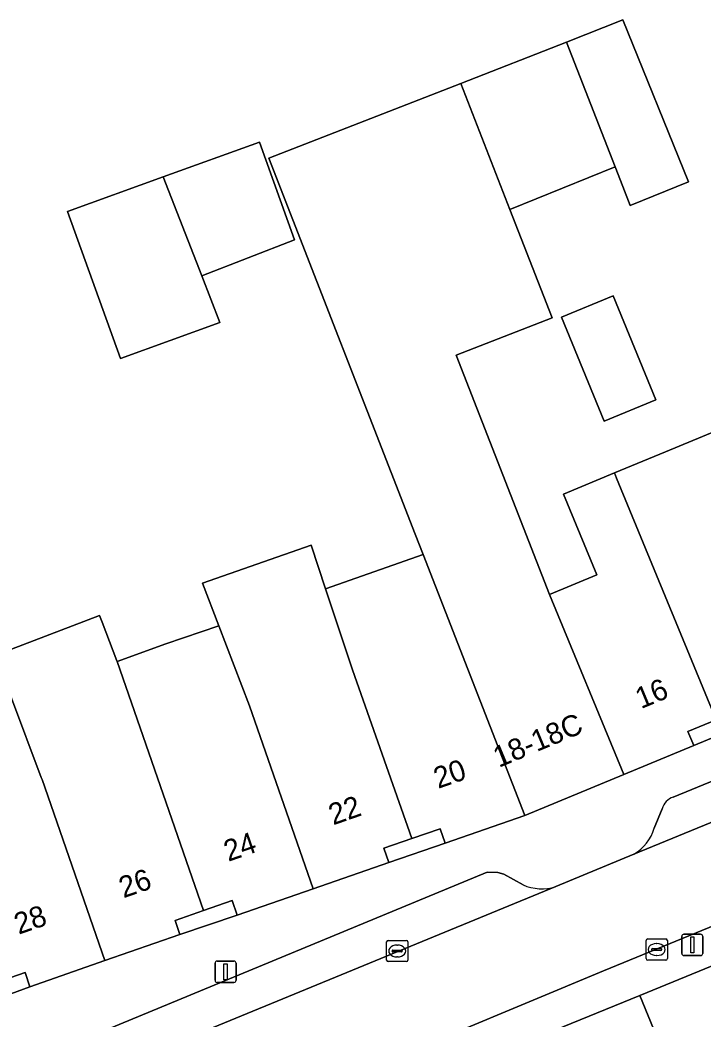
# Model space of a CAD drawing. Extents: x 159371 to 159986, y 382987 to 383597.
# Drawn here: x 159845.76 to 159877.92, y 383356.32 to 383403.35 of the extents above; entities that cross this region are included whole.
import ezdxf

# ---------------------------------------------------------------- set-up
doc = ezdxf.new("R2010")
doc.units = 0
for name, color, linetype in [('IMGEO_Erf', 7, 'Continuous'), ('IMGEO_Kolk', 7, 'Continuous'), ('IMGEO_Lichtmast', 7, 'Continuous'), ('IMGEO_Pand', 7, 'Continuous'), ('IMGEO_Pand_nummerreeks', 7, 'Continuous'), ('IMGEO_Parkeervlak_open', 7, 'Continuous'), ('IMGEO_Rijbaan_lokaal_open', 7, 'Continuous'), ('IMGEO_Voetpad_open', 7, 'Continuous')]:
    doc.layers.add(name, color=color, linetype=linetype)

msp = doc.modelspace()

# ---------------------------------------------------------------- linework, layer by layer
at = {"layer": 'IMGEO_Erf'}
msp.add_lwpolyline([(159844.604, 383373.459), (159849.507, 383375.324), (159849.63, 383375), (159850.322, 383373.18), (159850.332, 383373.15), (159852.636, 383373.984), (159855.129, 383374.826), (159854.362, 383376.837), (159859.474, 383378.624), (159860.151, 383376.581), (159864.746, 383378.187), (159864.374, 383379.142), (159857.484, 383396.843), (159866.523, 383400.361), (159871.498, 383402.313), (159874.144, 383403.352), (159877.244, 383395.735), (159874.499, 383394.618), (159874.152, 383395.509), (159873.786, 383396.446), (159868.832, 383394.43), (159870.814, 383389.337), (159866.298, 383387.579), (159870.687, 383376.303), (159872.924, 383377.231), (159871.349, 383381.03), (159873.758, 383382.028), (159876.16, 383383.024), (159878.542, 383384.012)], dxfattribs=at)
for points in [[(159852.508, 383395.963), (159857.034, 383397.596), (159858.688, 383393.009), (159854.324, 383391.307), (159855.181, 383389.109), (159850.492, 383387.418), (159847.997, 383394.337)], [(159871.261, 383389.365), (159873.687, 383390.362), (159875.7, 383385.467), (159873.274, 383384.47)]]:
    msp.add_lwpolyline(points, close=True, dxfattribs=at)
at = {"layer": 'IMGEO_Kolk'}
for p, q in [((159863.022, 383359.098), (159863.022, 383359.95)), ((159863.097, 383360.024), (159863.949, 383360.024)), ((159863.51, 383359.804), (159863.535, 383359.804)), ((159864.023, 383359.95), (159864.023, 383359.098)), ((159875.241, 383359.169), (159875.241, 383360.021)), ((159875.316, 383360.095), (159876.168, 383360.095)), ((159875.729, 383359.875), (159875.754, 383359.875)), ((159876.242, 383360.021), (159876.242, 383359.169)), ((159863.281, 383359.518), (159863.281, 383359.53)), ((159863.719, 383359.481), (159863.321, 383359.481)), ((159863.324, 383359.567), (159863.722, 383359.567)), ((159863.533, 383359.244), (159863.508, 383359.244)), ((159863.765, 383359.53), (159863.765, 383359.518)), ((159875.5, 383359.589), (159875.5, 383359.601)), ((159875.938, 383359.552), (159875.54, 383359.552)), ((159875.543, 383359.638), (159875.941, 383359.638)), ((159875.752, 383359.315), (159875.727, 383359.315)), ((159875.984, 383359.601), (159875.984, 383359.589)), ((159863.949, 383359.024), (159863.097, 383359.024)), ((159876.168, 383359.095), (159875.316, 383359.095))]:
    msp.add_line(p, q, dxfattribs=at)
for points in [[(159863.022, 383359.098), (159863.022, 383359.95)], [(159863.097, 383360.024), (159863.949, 383360.024)], [(159864.023, 383359.95), (159864.023, 383359.098)], [(159875.241, 383359.169), (159875.241, 383360.021)], [(159875.316, 383360.095), (159876.168, 383360.095)], [(159876.242, 383360.021), (159876.242, 383359.169)], [(159863.949, 383359.024), (159863.097, 383359.024)], [(159876.168, 383359.095), (159875.316, 383359.095)]]:
    msp.add_lwpolyline(points, dxfattribs=at)
for centre, radius, start, end in [((159863.099, 383359.948), 0.0765, 91.552, 178.448), ((159863.099, 383359.948), 0.0765, 91.552, 178.448), ((159863.947, 383359.948), 0.0765, 1.552, 88.448), ((159863.947, 383359.948), 0.0765, 1.552, 88.448), ((159875.318, 383360.019), 0.0765, 91.552, 178.448), ((159875.318, 383360.019), 0.0765, 91.552, 178.448), ((159876.166, 383360.019), 0.0765, 1.552, 88.448), ((159876.166, 383360.019), 0.0765, 1.552, 88.448), ((159863.321, 383359.527), 0.0403, 85.8775, 175.7526), ((159863.318, 383359.517), 0.0366, 178.938, 274.7102), ((159863.722, 383359.524), 0.043, 264.8664, 352.4533), ((159863.726, 383359.529), 0.0386, 1.7309, 96.639), ((159875.54, 383359.598), 0.0403, 85.8775, 175.7526), ((159875.537, 383359.588), 0.0366, 178.938, 274.7102), ((159875.941, 383359.595), 0.043, 264.8664, 352.4533), ((159875.945, 383359.6), 0.0386, 1.7309, 96.639), ((159863.099, 383359.1), 0.0765, 181.552, 268.448), ((159863.099, 383359.1), 0.0765, 181.552, 268.448), ((159863.947, 383359.1), 0.0765, 271.552, 358.448), ((159863.947, 383359.1), 0.0765, 271.552, 358.448), ((159875.318, 383359.171), 0.0765, 181.552, 268.448), ((159875.318, 383359.171), 0.0765, 181.552, 268.448), ((159876.166, 383359.171), 0.0765, 271.552, 358.448), ((159876.166, 383359.171), 0.0765, 271.552, 358.448)]:
    msp.add_arc(centre, radius, start, end, dxfattribs=at)
for centre, major_axis, ratio, start_param, end_param in [((159863.509, 383359.524), (-0.387, 0.002), 0.722429, 4.712389, 7.853982), ((159863.534, 383359.524), (-0.39, 0.002), 0.717154, 1.570796, 4.712389), ((159875.728, 383359.595), (-0.387, 0.002), 0.722429, 4.712389, 7.853982), ((159875.753, 383359.595), (-0.39, 0.002), 0.717154, 1.570796, 4.712389)]:
    msp.add_ellipse(centre, major_axis=major_axis, ratio=ratio, start_param=start_param, end_param=end_param, dxfattribs=at)
at = {"layer": 'IMGEO_Lichtmast'}
for p, q in [((159876.92, 383359.411), (159876.92, 383360.211)), ((159876.92, 383360.211), (159876.92, 383359.411)), ((159877.02, 383360.311), (159877.81, 383360.311)), ((159877.81, 383360.311), (159877.02, 383360.311)), ((159877.91, 383360.211), (159877.91, 383359.411)), ((159877.91, 383359.411), (159877.91, 383360.211)), ((159877.81, 383359.311), (159877.02, 383359.311)), ((159877.02, 383359.311), (159877.81, 383359.311)), ((159854.947, 383358.15), (159854.947, 383358.95)), ((159854.947, 383358.95), (159854.947, 383358.15)), ((159855.047, 383359.05), (159855.837, 383359.05)), ((159855.837, 383359.05), (159855.047, 383359.05)), ((159855.937, 383358.95), (159855.937, 383358.15)), ((159855.937, 383358.15), (159855.937, 383358.95)), ((159855.837, 383358.05), (159855.047, 383358.05)), ((159855.047, 383358.05), (159855.837, 383358.05))]:
    msp.add_line(p, q, dxfattribs=at)
for points in [[(159877.34, 383360.186), (159877.49, 383360.186), (159877.49, 383359.436), (159877.34, 383359.436), (159877.34, 383360.186)], [(159855.367, 383358.925), (159855.517, 383358.925), (159855.517, 383358.175), (159855.367, 383358.175), (159855.367, 383358.925)]]:
    msp.add_lwpolyline(points, dxfattribs=at)
for centre, start, end in [((159877.02, 383360.211), 90, 180), ((159877.02, 383360.211), 90, 180), ((159877.81, 383360.211), 0, 90), ((159877.81, 383360.211), 360, 90), ((159877.02, 383359.411), 180, 270), ((159877.02, 383359.411), 180, 270), ((159877.81, 383359.411), 270, 0), ((159877.81, 383359.411), 270, 0), ((159855.047, 383358.95), 90, 180), ((159855.047, 383358.95), 90, 180), ((159855.837, 383358.95), 0, 90), ((159855.837, 383358.95), 360, 90), ((159855.047, 383358.15), 180, 270), ((159855.047, 383358.15), 180, 270), ((159855.837, 383358.15), 270, 0), ((159855.837, 383358.15), 270, 0)]:
    msp.add_arc(centre, 0.1, start, end, dxfattribs=at)
at = {"layer": 'IMGEO_Pand'}
for points in [[(159874.144, 383403.352), (159871.498, 383402.313), (159873.786, 383396.446), (159874.152, 383395.509), (159874.499, 383394.618), (159877.244, 383395.735)], [(159871.498, 383402.313), (159866.523, 383400.361), (159868.832, 383394.43), (159873.786, 383396.446)], [(159866.298, 383387.579), (159870.814, 383389.337), (159868.832, 383394.43), (159866.523, 383400.361), (159857.484, 383396.843), (159864.374, 383379.142), (159864.746, 383378.187), (159869.526, 383365.904), (159874.188, 383367.836), (159870.687, 383376.303)], [(159857.034, 383397.596), (159852.508, 383395.963), (159854.324, 383391.307), (159858.688, 383393.009)], [(159852.508, 383395.963), (159847.997, 383394.337), (159850.492, 383387.418), (159855.181, 383389.109), (159854.324, 383391.307)], [(159871.261, 383389.365), (159873.274, 383384.47), (159875.7, 383385.467), (159873.687, 383390.362)], [(159880.125, 383380.191), (159878.542, 383384.012), (159876.16, 383383.024), (159873.758, 383382.028), (159873.844, 383381.791), (159878.538, 383370.408), (159879.863, 383370.957), (159880.134, 383370.303), (159883.622, 383371.749)], [(159874.188, 383367.836), (159877.483, 383369.202), (159877.211, 383369.858), (159878.538, 383370.408), (159873.844, 383381.791), (159873.758, 383382.028), (159871.349, 383381.03), (159872.924, 383377.231), (159870.687, 383376.303)], [(159861.419, 383372.755), (159860.151, 383376.581), (159859.474, 383378.624), (159854.362, 383376.837), (159855.129, 383374.826), (159856.563, 383371.068), (159859.561, 383362.457), (159863.132, 383363.697), (159862.9, 383364.364), (159864.22, 383364.823)], [(159864.746, 383378.187), (159860.151, 383376.581), (159861.419, 383372.755), (159864.22, 383364.823), (159865.539, 383365.281), (159865.775, 383364.603), (159869.526, 383365.904)], [(159850.332, 383373.15), (159850.322, 383373.18), (159849.63, 383375), (159849.507, 383375.324), (159844.604, 383373.459), (159844.726, 383373.135), (159845.368, 383371.426), (159846.769, 383367.697), (159846.807, 383367.595), (159849.765, 383359.071), (159853.295, 383360.297), (159853.064, 383360.962), (159854.41, 383361.429)], [(159856.563, 383371.068), (159855.129, 383374.826), (159852.636, 383373.984), (159850.332, 383373.15), (159854.41, 383361.429), (159855.757, 383361.897), (159855.993, 383361.217), (159859.561, 383362.457)], [(159846.807, 383367.595), (159846.769, 383367.697), (159845.368, 383371.426), (159842.919, 383370.575), (159840.573, 383369.76), (159844.638, 383358.043), (159846.002, 383358.517), (159846.235, 383357.845), (159849.765, 383359.071)], [(159874.945, 383357.438), (159878.193, 383349.504), (159880.635, 383350.504), (159881.789, 383347.688), (159884.593, 383348.837), (159883.363, 383351.84), (159880.193, 383359.588)]]:
    msp.add_lwpolyline(points, close=True, dxfattribs=at)
msp.add_lwpolyline([(159883.83, 383337.841), (159889.843, 383341.082), (159889.525, 383343.991), (159884.017, 383344.028), (159879.706, 383344.612), (159879.828, 383345.513), (159878.193, 383349.504), (159874.945, 383357.438), (159866.522, 383353.987), (159865.29, 383351.045), (159869.208, 383341.301), (159881.598, 383339.216), (159881.331, 383337.761), (159881.859, 383337.661), (159882.174, 383337.602)], dxfattribs=at)
at = {"layer": 'IMGEO_Parkeervlak_open'}
for points in [[(159910.848, 383380.871), (159876.516, 383366.772)], [(159874.665, 383364.08), (159894.206, 383372.109), (159896.76, 383373.158), (159914.033, 383380.255)], [(159875.992, 383366.224), (159875.627, 383365.304)], [(159869.447, 383362.64), (159868.544, 383363.141), (159868.256, 383363.221), (159867.764, 383363.229), (159843.667, 383353.269)], [(159844.401, 383351.626), (159846.413, 383352.453), (159852.647, 383355.016), (159870.989, 383362.556)]]:
    msp.add_lwpolyline(points, dxfattribs=at)
for centre, radius, start, end in [((159876.846, 383365.932), 0.903, 111.4543, 161.1108), ((159873.547, 383365.949), 2.178, 300.8954, 342.7736), ((159870.329, 383364.635), 2.181, 246.152, 287.6118)]:
    msp.add_arc(centre, radius, start, end, dxfattribs=at)
at = {"layer": 'IMGEO_Rijbaan_lokaal_open'}
msp.add_lwpolyline([(159855.412, 383349.492), (159862.546, 383354.138), (159873.236, 383358.594), (159895.93, 383367.9), (159894.206, 383372.109), (159874.665, 383364.08), (159870.989, 383362.556), (159852.647, 383355.016), (159854.94, 383349.623), (159855.086, 383349.291)], dxfattribs=at)
at = {"layer": 'IMGEO_Voetpad_open'}
for points in [[(159876.516, 383366.772), (159910.848, 383380.871)], [(159869.905, 383339.262), (159881.768, 383337.219), (159881.859, 383337.661), (159881.331, 383337.761), (159869.846, 383339.731), (159869.208, 383341.301), (159865.29, 383351.045), (159866.522, 383353.987), (159874.945, 383357.438), (159880.193, 383359.588), (159886.8, 383362.295), (159892.526, 383364.641), (159899.783, 383367.614), (159906.767, 383370.475), (159906.023, 383372.039), (159898.484, 383368.948), (159895.93, 383367.9), (159873.236, 383358.594), (159862.546, 383354.138), (159855.412, 383349.492)], [(159880.134, 383370.303), (159877.483, 383369.202), (159874.188, 383367.836), (159869.526, 383365.904), (159865.775, 383364.603), (159863.132, 383363.697), (159859.561, 383362.457), (159855.993, 383361.217), (159853.295, 383360.297), (159849.765, 383359.071), (159846.235, 383357.845), (159843.522, 383356.857)], [(159875.627, 383365.304), (159875.992, 383366.224)], [(159870.989, 383362.556), (159874.665, 383364.08)], [(159843.667, 383353.269), (159867.764, 383363.229), (159868.256, 383363.221), (159868.544, 383363.141), (159869.447, 383362.64)]]:
    msp.add_lwpolyline(points, dxfattribs=at)
for points in [[(159880.134, 383370.303), (159879.863, 383370.957), (159878.538, 383370.408), (159877.211, 383369.858), (159877.483, 383369.202)], [(159865.775, 383364.603), (159865.539, 383365.281), (159864.22, 383364.823), (159862.9, 383364.364), (159863.132, 383363.697)], [(159855.993, 383361.217), (159855.757, 383361.897), (159854.41, 383361.429), (159853.064, 383360.962), (159853.295, 383360.297)], [(159846.235, 383357.845), (159846.002, 383358.517), (159844.638, 383358.043), (159843.274, 383357.57), (159843.522, 383356.857)]]:
    msp.add_lwpolyline(points, close=True, dxfattribs=at)
for centre, radius, start, end in [((159876.846, 383365.932), 0.903, 111.4543, 161.1108), ((159873.547, 383365.949), 2.178, 300.8954, 342.7736), ((159870.329, 383364.635), 2.181, 246.152, 287.6118)]:
    msp.add_arc(centre, radius, start, end, dxfattribs=at)

# ---------------------------------------------------------------- texts
at = {"layer": 'IMGEO_Pand_nummerreeks'}
for s, rotation, p in [('16', 22.5624, (159874.999, 383370.908)), ('18-18C', 22.6891, (159868.308, 383368.144)), ('20', 19.1769, (159865.451, 383367.156)), ('22', 19.1769, (159860.507, 383365.437)), ('24', 19.1769, (159855.573, 383363.721)), ('26', 19.1769, (159850.636, 383362.004)), ('28', 19.1769, (159845.702, 383360.288))]:
    msp.add_text(s, height=1, rotation=rotation, dxfattribs=at).set_placement(p)

doc.saveas('drawing.dxf')
